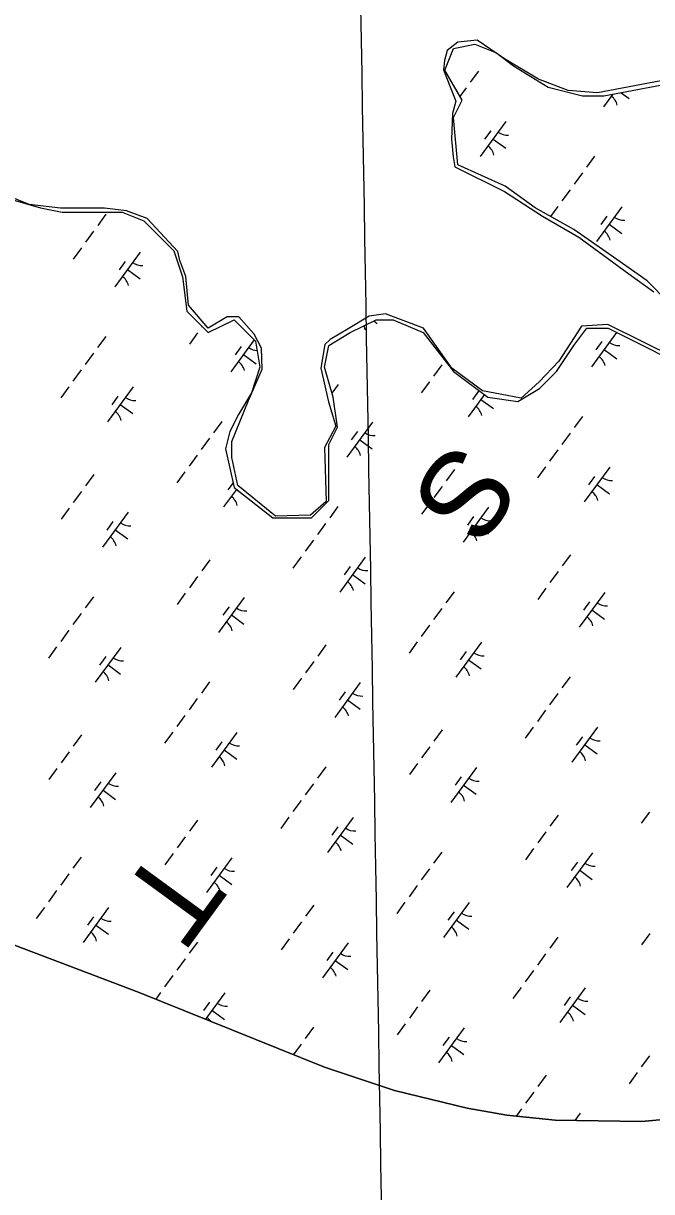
# Model space of a CAD drawing. Extents: x 3905714 to 3926767, y 183354 to 205755.
# Drawn here: x 3914338 to 3915064, y 194998 to 196348 of the extents above; entities that cross this region are included whole.
import ezdxf

# ---------------------------------------------------------------- set-up
doc = ezdxf.new("R2010")
doc.units = 0
for name, color, linetype in [('V-GRID-MAJR', 7, 'Continuous'), ('V-RIVR-IDEN', 7, 'Continuous'), ('V-TOPO-SHOR', 7, 'Continuous'), ('V-WETL-SWMP', 7, 'Continuous')]:
    doc.layers.add(name, color=color, linetype=linetype)

msp = doc.modelspace()

# ---------------------------------------------------------------- linework, layer by layer
at = {"layer": 'V-GRID-MAJR'}
msp.add_spline([(3914930.2, 184667.8), (3914884.1, 187327.4), (3914779.2, 193387.5), (3914694.6, 198275.9)], degree=3, dxfattribs=at)
at = {"layer": 'V-TOPO-SHOR'}
for points in [[(3915080.3, 196282.9), (3915001, 196267.7), (3914967.2, 196270.4), (3914932.7, 196283.7), (3914893.6, 196307.2), (3914861.8, 196328.8), (3914839.5, 196326.4), (3914827.3, 196316.6), (3914824.1, 196305.3), (3914822.9, 196294.3), (3914830.8, 196274.9), (3914837.3, 196258.2), (3914833.6, 196243.9), (3914832.3, 196214.2), (3914834.4, 196193.8), (3914836.2, 196182.3), (3914893.7, 196153.8), (3914937.5, 196125.2), (3914979.5, 196101.2), (3915037.2, 196058.9), (3915066, 196037.8)], [(3915091.6, 195961.1), (3915012.8, 196000.1), (3914982.6, 195998.4), (3914956.4, 195958), (3914933.6, 195933.8), (3914912.9, 195914.9), (3914896.6, 195918.3), (3914868.2, 195923.7), (3914832.8, 195949.7), (3914800.1, 195995.8), (3914756.2, 196012.6), (3914737, 196009.7), (3914712.7, 195995.1), (3914691.9, 195983), (3914685.9, 195977.2), (3914681.3, 195949.9), (3914690.2, 195911), (3914698.5, 195882.8), (3914685.6, 195858.2), (3914687.4, 195795.5), (3914669.2, 195779.9), (3914629, 195778.6), (3914585.2, 195814.2), (3914578.3, 195846.5), (3914578.3, 195865.2), (3914597.6, 195912.4), (3914613.7, 195948.4), (3914612.9, 195972.8), (3914604.4, 195989.2), (3914586.6, 196009.1), (3914572.9, 196008.9), (3914551.3, 195995.8), (3914528.4, 196022.7), (3914525.3, 196055.7), (3914518.5, 196074.3), (3914515.9, 196084.7), (3914480.6, 196122.5), (3914456.6, 196131.6), (3914431.5, 196134.6), (3914380.4, 196134.6), (3914344.3, 196138.9), (3914308.7, 196153)], [(3914307.8, 195290.6), (3914471.5, 195228.6), (3914685.7, 195142.2), (3914766.5, 195115.1), (3914850.5, 195094.7), (3914896.4, 195086.6), (3914952.2, 195081.1), (3915052, 195079.4), (3915135.6, 195087.3), (3915182.7, 195097.5), (3915234.5, 195117.5), (3915279.1, 195147.6), (3915332.6, 195191.7), (3915406.2, 195262.3), (3915585.5, 195470.7), (3915629.7, 195526.8), (3915716.6, 195642.8), (3915879.3, 195871.2)]]:
    msp.add_lwpolyline(points, dxfattribs=at)
at = {"layer": 'V-WETL-SWMP'}
for p, q in [((3914834.5, 196319), (3914859.4, 196323.9)), ((3914859.4, 196323.9), (3914884.2, 196314)), ((3914824.6, 196294.1), (3914834.5, 196319)), ((3914884.2, 196314), (3914904.1, 196299.1)), ((3914904.1, 196299.1), (3914943.9, 196274.2)), ((3914844.5, 196259.3), (3914824.6, 196294.1)), ((3914863.5, 196293), (3914854, 196280.1)), ((3914849.3, 196273.6), (3914842, 196263.6)), ((3914943.9, 196274.2), (3914983.6, 196264.3)), ((3915008.5, 196264.3), (3915088, 196279.2)), ((3914834.5, 196239.4), (3914844.5, 196259.3)), ((3914983.6, 196264.3), (3915008.5, 196264.3)), ((3915018.6, 196266.2), (3915008.1, 196251.8)), ((3915028.3, 196268), (3915037.4, 196261.4)), ((3914839.5, 196184.7), (3914834.5, 196239.4)), ((3914895.1, 196234.6), (3914865.6, 196194.2)), ((3914877.7, 196223.8), (3914870.6, 196214.1)), ((3914880.3, 196214.4), (3914894.9, 196203.8)), ((3914997.7, 196194.7), (3914988.2, 196181.8)), ((3914894.2, 196159.8), (3914839.5, 196184.7)), ((3914983.5, 196175.3), (3914974, 196162.4)), ((3914929, 196135), (3914894.2, 196159.8)), ((3914969.3, 196155.9), (3914959.8, 196143)), ((3914322.7, 196144.9), (3914357.4, 196135)), ((3914357.4, 196135), (3914382.3, 196130)), ((3914973.7, 196110.1), (3914929, 196135)), ((3914955.1, 196136.6), (3914946.7, 196125.1)), ((3915029.3, 196136.3), (3914999.7, 196095.9)), ((3914382.3, 196130), (3914451.9, 196130)), ((3914433, 196127.5), (3914423.6, 196114.6)), ((3914451.9, 196130), (3914476.7, 196120.1)), ((3915011.8, 196125.5), (3915004.7, 196115.8)), ((3914418.8, 196108.1), (3914409.4, 196095.2)), ((3914476.7, 196120.1), (3914511.5, 196085.3)), ((3915023.4, 196075.3), (3914973.7, 196110.1)), ((3915014.5, 196116.1), (3915029, 196105.4)), ((3914404.7, 196088.7), (3914395.2, 196075.8)), ((3914472.7, 196083.9), (3914443.1, 196043.6)), ((3914511.5, 196085.3), (3914521.4, 196055.4)), ((3914455.2, 196073.1), (3914448.1, 196063.5)), ((3915058.2, 196050.5), (3915023.4, 196075.3)), ((3914457.9, 196063.7), (3914472.4, 196053.1)), ((3914521.4, 196055.4), (3914526.4, 196015.7)), ((3915083, 196025.6), (3915058.2, 196050.5)), ((3914526.4, 196015.7), (3914551.3, 195990.8)), ((3914551.3, 195990.8), (3914581.1, 196005.7)), ((3914581.1, 196005.7), (3914605.9, 195980.8)), ((3914715.3, 195990.8), (3914745.1, 196005.7)), ((3914742.4, 196004.4), (3914746.5, 196001.3)), ((3914745.1, 196005.7), (3914765, 196005.7)), ((3914765, 196005.7), (3914799.7, 195990.8)), ((3914432.7, 195986.4), (3914423.2, 195973.5)), ((3914538.8, 195990.4), (3914529.4, 195977.5)), ((3914544.2, 195997.8), (3914543.6, 195996.9)), ((3914690.4, 195975.9), (3914715.3, 195990.8)), ((3914799.7, 195990.8), (3914834.5, 195946)), ((3914973.7, 195975.9), (3914988.6, 195995.8)), ((3914988.6, 195995.8), (3915013.4, 195995.8)), ((3915023.1, 195990.9), (3914994, 195951.1)), ((3915013.4, 195995.8), (3915043.3, 195980.8)), ((3914604.4, 195982.3), (3914577.3, 195945.3)), ((3914589.4, 195974.8), (3914582.3, 195965.2)), ((3914605.9, 195980.8), (3914610.9, 195951)), ((3914685.4, 195951), (3914690.4, 195975.9)), ((3914953.8, 195946), (3914973.7, 195975.9)), ((3915006.1, 195980.7), (3914999, 195971)), ((3915043.3, 195980.8), (3915093, 195956)), ((3914418.5, 195967), (3914409, 195954.1)), ((3914592.1, 195965.4), (3914606.6, 195954.8)), ((3915008.7, 195971.3), (3915023.3, 195960.6)), ((3914404.3, 195947.7), (3914394.8, 195934.8)), ((3914610.9, 195951), (3914601, 195921.2)), ((3914695.4, 195916.2), (3914685.4, 195951)), ((3914821, 195953.5), (3914811.5, 195940.6)), ((3914834.5, 195946), (3914874.3, 195916.2)), ((3914933.9, 195926.1), (3914953.8, 195946)), ((3914806.8, 195934.1), (3914797.3, 195921.2)), ((3914390.1, 195928.3), (3914380.7, 195915.4)), ((3914464.3, 195928), (3914434.8, 195887.7)), ((3914601, 195921.2), (3914586, 195896.3)), ((3914701.4, 195930.9), (3914694.1, 195920.8)), ((3914870.3, 195919.2), (3914851.4, 195893.5)), ((3914863.5, 195923), (3914856.4, 195913.4)), ((3914909.1, 195911.2), (3914933.9, 195926.1)), ((3914446.9, 195917.2), (3914439.8, 195907.5)), ((3914449.5, 195907.8), (3914464, 195897.2)), ((3914700.4, 195881.4), (3914695.4, 195916.2)), ((3914866.2, 195913.6), (3914880.7, 195903)), ((3914874.3, 195916.2), (3914909.1, 195911.2)), ((3914586, 195896.3), (3914576.1, 195876.4)), ((3914983.5, 195893.9), (3914974.1, 195881)), ((3914566.9, 195888.1), (3914557.4, 195875.2)), ((3914690.4, 195861.5), (3914700.4, 195881.4)), ((3914741, 195887.3), (3914711.5, 195847)), ((3914552.7, 195868.7), (3914543.2, 195855.8)), ((3914576.1, 195876.4), (3914571.1, 195856.5)), ((3914723.6, 195876.5), (3914716.5, 195866.9)), ((3914726.2, 195867.1), (3914740.8, 195856.5)), ((3914969.3, 195874.6), (3914959.9, 195861.7)), ((3914571.1, 195856.5), (3914581.1, 195811.8)), ((3914690.4, 195831.7), (3914690.4, 195861.5)), ((3914955.2, 195855.2), (3914945.7, 195842.3)), ((3914538.5, 195849.4), (3914529, 195836.5)), ((3914418.9, 195826.7), (3914409.4, 195813.8)), ((3914524.3, 195830), (3914514.8, 195817.1)), ((3914690.4, 195796.9), (3914690.4, 195831.7)), ((3914835.6, 195832.5), (3914826.1, 195819.6)), ((3914941, 195835.8), (3914931.5, 195822.9)), ((3915015.2, 195835.5), (3914985.6, 195795.2)), ((3914997.7, 195824.7), (3914990.6, 195815.1)), ((3914579.9, 195817.3), (3914573.9, 195809.2)), ((3914581.1, 195811.8), (3914625.8, 195777)), ((3914821.4, 195813.2), (3914811.9, 195800.3)), ((3915000.4, 195815.3), (3915014.9, 195804.7)), ((3914404.7, 195807.4), (3914395.2, 195794.5)), ((3914583.8, 195809.7), (3914568.9, 195789.4)), ((3914583.7, 195809.5), (3914588.6, 195805.9)), ((3914390.5, 195788), (3914381.1, 195775.1)), ((3914670.5, 195777), (3914690.4, 195796.9)), ((3914701, 195789.8), (3914691.6, 195776.9)), ((3914807.2, 195793.8), (3914797.7, 195780.9)), ((3914875.2, 195789), (3914845.7, 195748.7)), ((3914458.5, 195783.2), (3914429, 195742.8)), ((3914441.1, 195772.4), (3914434, 195762.7)), ((3914625.8, 195777), (3914670.5, 195777)), ((3914686.8, 195770.4), (3914677.4, 195757.5)), ((3914857.7, 195778.2), (3914850.7, 195768.5)), ((3914443.8, 195763), (3914458.3, 195752.4)), ((3914860.4, 195768.8), (3914874.9, 195758.2)), ((3914672.7, 195751.1), (3914663.2, 195738.2)), ((3914658.5, 195731.7), (3914649, 195718.8)), ((3914732.7, 195731.4), (3914703.1, 195691)), ((3914969.7, 195734.2), (3914960.3, 195721.3)), ((3914553.1, 195728.4), (3914543.6, 195715.5)), ((3914715.2, 195720.6), (3914708.1, 195710.9)), ((3914538.9, 195709.1), (3914529.4, 195696.1)), ((3914717.9, 195711.2), (3914732.4, 195700.6)), ((3914955.6, 195714.9), (3914946.1, 195702)), ((3914524.7, 195689.7), (3914515.2, 195676.8)), ((3914835.2, 195691.5), (3914825.8, 195678.6)), ((3914941.4, 195695.5), (3914931.9, 195682.6)), ((3915009.4, 195690.7), (3914979.8, 195650.4)), ((3914418.5, 195685.7), (3914409.1, 195672.7)), ((3914592.7, 195684.9), (3914563.2, 195644.5)), ((3914991.9, 195679.9), (3914984.8, 195670.2)), ((3914404.4, 195666.3), (3914394.9, 195653.4)), ((3914575.3, 195674.1), (3914568.2, 195664.4)), ((3914577.9, 195664.7), (3914592.5, 195654.1)), ((3914821, 195672.1), (3914811.6, 195659.2)), ((3914994.6, 195670.5), (3915009.1, 195659.9)), ((3914806.8, 195652.8), (3914797.4, 195639.9)), ((3914390.2, 195646.9), (3914380.7, 195634)), ((3914376, 195627.6), (3914366.5, 195614.7)), ((3914450.2, 195627.2), (3914420.6, 195586.9)), ((3914687.2, 195630.1), (3914677.8, 195617.2)), ((3914792.7, 195633.4), (3914783.2, 195620.5)), ((3914866.8, 195633.1), (3914837.3, 195592.7)), ((3914849.4, 195622.3), (3914842.3, 195612.6)), ((3914432.7, 195616.5), (3914425.6, 195606.8)), ((3914673.1, 195610.7), (3914663.6, 195597.8)), ((3914852.1, 195612.9), (3914866.6, 195602.3)), ((3914435.4, 195607.1), (3914449.9, 195596.4)), ((3914552.7, 195587.3), (3914543.3, 195574.4)), ((3914658.9, 195591.4), (3914649.4, 195578.5)), ((3914726.9, 195586.6), (3914697.3, 195546.2)), ((3914969.4, 195593.2), (3914959.9, 195580.3)), ((3914538.5, 195568), (3914529.1, 195555.1)), ((3914709.4, 195575.8), (3914702.3, 195566.1)), ((3914955.2, 195573.8), (3914945.7, 195560.9)), ((3914712.1, 195566.4), (3914726.6, 195555.8)), ((3914941, 195554.5), (3914931.6, 195541.5)), ((3914524.3, 195548.6), (3914514.9, 195535.7)), ((3914510.2, 195529.3), (3914500.7, 195516.4)), ((3914584.3, 195528.9), (3914554.8, 195488.6)), ((3914821.4, 195531.8), (3914812, 195518.9)), ((3914926.8, 195535.1), (3914917.4, 195522.2)), ((3915001, 195534.8), (3914971.5, 195494.4)), ((3914404.8, 195526), (3914395.3, 195513.1)), ((3914566.9, 195518.2), (3914559.8, 195508.5)), ((3914983.6, 195524), (3914976.5, 195514.3)), ((3914986.2, 195514.6), (3915000.8, 195504)), ((3914390.6, 195506.6), (3914381.1, 195493.7)), ((3914569.6, 195508.8), (3914584.1, 195498.1)), ((3914807.2, 195512.4), (3914797.8, 195499.5)), ((3914376.4, 195487.3), (3914366.9, 195474.4)), ((3914686.9, 195489), (3914677.4, 195476.1)), ((3914793.1, 195493.1), (3914783.6, 195480.2)), ((3914861.1, 195488.3), (3914831.5, 195447.9)), ((3914444.4, 195482.4), (3914414.8, 195442.1)), ((3914843.6, 195477.5), (3914836.5, 195467.8)), ((3914426.9, 195471.7), (3914419.8, 195462)), ((3914429.6, 195462.3), (3914444.1, 195451.6)), ((3914672.7, 195469.7), (3914663.3, 195456.8)), ((3914846.3, 195468.1), (3914860.8, 195457.4)), ((3914658.5, 195450.3), (3914649.1, 195437.4)), ((3914955.6, 195433.5), (3914946.1, 195420.6)), ((3915061, 195436.8), (3915051.6, 195423.9)), ((3914538.9, 195427.7), (3914529.5, 195414.8)), ((3914644.3, 195431), (3914634.9, 195418.1)), ((3914718.5, 195430.6), (3914689, 195390.3)), ((3914701.1, 195419.9), (3914694, 195410.2)), ((3914524.7, 195408.3), (3914515.3, 195395.4)), ((3914703.8, 195410.5), (3914718.3, 195399.8)), ((3914941.4, 195414.1), (3914932, 195401.2)), ((3914927.2, 195394.8), (3914917.8, 195381.9)), ((3914404.4, 195384.9), (3914394.9, 195372)), ((3914510.6, 195389), (3914501.1, 195376)), ((3914578.6, 195384.1), (3914549, 195343.8)), ((3914821.1, 195390.7), (3914811.6, 195377.8)), ((3914995.2, 195389.9), (3914965.7, 195349.6)), ((3914977.8, 195379.2), (3914970.7, 195369.5)), ((3914390.2, 195365.6), (3914380.8, 195352.6)), ((3914561.1, 195373.4), (3914554, 195363.7)), ((3914806.9, 195371.4), (3914797.4, 195358.5)), ((3914980.5, 195369.8), (3914995, 195359.1)), ((3914563.8, 195364), (3914578.3, 195353.3)), ((3914792.7, 195352), (3914783.3, 195339.1)), ((3914376, 195346.2), (3914366.6, 195333.3)), ((3914361.8, 195326.8), (3914352.4, 195313.9)), ((3914436, 195326.5), (3914406.5, 195286.2)), ((3914673.1, 195329.4), (3914663.7, 195316.5)), ((3914778.5, 195332.7), (3914769.1, 195319.8)), ((3914852.7, 195332.3), (3914823.2, 195292)), ((3914418.6, 195315.7), (3914411.5, 195306.1)), ((3914835.3, 195321.6), (3914828.2, 195311.9)), ((3914837.9, 195312.2), (3914852.5, 195301.5)), ((3914421.3, 195306.3), (3914435.8, 195295.7)), ((3914658.9, 195310), (3914649.5, 195297.1)), ((3914471.5, 195228.6), (3914307.8, 195290.6)), ((3914538.6, 195286.6), (3914529.1, 195273.7)), ((3914644.7, 195290.6), (3914635.3, 195277.7)), ((3914712.8, 195285.8), (3914683.2, 195245.5)), ((3914955.3, 195292.4), (3914945.8, 195279.5)), ((3915061.4, 195296.5), (3915052, 195283.6)), ((3914695.3, 195275), (3914688.2, 195265.4)), ((3914941.1, 195273.1), (3914931.6, 195260.2)), ((3914524.4, 195267.2), (3914514.9, 195254.3)), ((3914698, 195265.6), (3914712.5, 195255)), ((3914510.2, 195247.9), (3914500.8, 195235)), ((3914926.9, 195253.7), (3914917.4, 195240.8)), ((3914807.3, 195231.1), (3914797.8, 195218.2)), ((3914912.7, 195234.4), (3914903.2, 195221.4)), ((3914986.9, 195234), (3914957.3, 195193.7)), ((3914685.7, 195142.2), (3914471.5, 195228.6)), ((3914496, 195228.5), (3914490.5, 195220.9)), ((3914552.8, 195217.4), (3914545.7, 195207.8)), ((3914570.2, 195228.2), (3914547.9, 195197.7)), ((3914969.4, 195223.3), (3914962.3, 195213.6)), ((3914555.4, 195208), (3914570, 195197.4)), ((3914793.1, 195211.7), (3914783.7, 195198.8)), ((3914972.1, 195213.9), (3914986.6, 195203.2)), ((3914778.9, 195192.3), (3914769.5, 195179.4)), ((3914672.8, 195188.3), (3914663.3, 195175.4)), ((3914846.9, 195187.5), (3914817.4, 195147.2)), ((3914829.5, 195176.7), (3914822.4, 195167.1)), ((3914658.6, 195168.9), (3914649.6, 195156.7)), ((3914832.2, 195167.3), (3914846.7, 195156.7)), ((3915061.1, 195155.4), (3915051.6, 195142.5)), ((3914766.5, 195115.1), (3914685.7, 195142.2)), ((3915046.9, 195136), (3915037.4, 195123.1)), ((3914941.5, 195132.8), (3914932, 195119.8)), ((3914850.5, 195094.7), (3914766.5, 195115.1)), ((3914927.3, 195113.4), (3914917.8, 195100.5)), ((3914896.4, 195086.6), (3914850.5, 195094.7)), ((3914952.2, 195081.1), (3914896.4, 195086.6)), ((3914913.1, 195094), (3914906.9, 195085.6)), ((3914981.1, 195089.2), (3914974.9, 195080.7)), ((3915135.6, 195087.3), (3915052, 195079.4)), ((3915052, 195079.4), (3914952.2, 195081.1))]:
    msp.add_line(p, q, dxfattribs=at)
for centre, start, end in [((3915006.7, 196249.6), 13, 54.5436), ((3914896.9, 196236.5), 233, 274.5436), ((3914864.2, 196192), 13, 54.5436), ((3915031, 196138.2), 233, 274.5436), ((3914998.4, 196093.7), 13, 54.5436), ((3914474.4, 196085.9), 233, 274.5436), ((3914441.8, 196041.3), 13, 54.5436), ((3914715.9, 195989.5), 13, 31.1544), ((3914608.6, 195987.6), 233, 267.2471), ((3915025.3, 195993.4), 233, 274.5436), ((3914992.6, 195948.8), 13, 54.5436), ((3914575.9, 195943), 13, 54.5436), ((3914466, 195930), 233, 274.5436), ((3914850.1, 195891.2), 13, 54.5436), ((3914433.4, 195885.4), 13, 54.5436), ((3914742.8, 195889.3), 233, 274.5436), ((3914710.1, 195844.7), 13, 54.5436), ((3915016.9, 195837.5), 233, 274.5436), ((3914567.6, 195787.1), 13, 54.5436), ((3914984.2, 195792.9), 13, 54.5436), ((3914460.3, 195785.1), 233, 274.5436), ((3914876.9, 195791), 233, 274.5436), ((3914844.3, 195746.4), 13, 54.5436), ((3914427.6, 195740.6), 13, 54.5436), ((3914734.4, 195733.4), 233, 274.5436), ((3914701.8, 195688.8), 13, 54.5436), ((3915011.1, 195692.7), 233, 274.5436), ((3914594.4, 195686.8), 233, 274.5436), ((3914978.5, 195648.1), 13, 54.5436), ((3914561.8, 195642.3), 13, 54.5436), ((3914451.9, 195629.2), 233, 274.5436), ((3914868.6, 195635), 233, 274.5436), ((3914419.3, 195584.7), 13, 54.5436), ((3914835.9, 195590.5), 13, 54.5436), ((3914728.6, 195588.5), 233, 274.5436), ((3914696, 195544), 13, 54.5436), ((3914586.1, 195530.9), 233, 274.5436), ((3915002.8, 195536.7), 233, 274.5436), ((3914553.4, 195486.4), 13, 54.5436), ((3914970.1, 195492.2), 13, 54.5436), ((3914862.8, 195490.2), 233, 274.5436), ((3914446.1, 195484.4), 233, 274.5436), ((3914830.2, 195445.7), 13, 54.5436), ((3914413.5, 195439.8), 13, 54.5436), ((3914720.3, 195432.6), 233, 274.5436), ((3914687.6, 195388), 13, 54.5436), ((3914580.3, 195386.1), 233, 274.5436), ((3914997, 195391.9), 233, 274.5436), ((3914547.7, 195341.5), 13, 54.5436), ((3914964.3, 195347.4), 13, 54.5436), ((3914437.8, 195328.5), 233, 274.5436), ((3914854.4, 195334.3), 233, 274.5436), ((3914405.1, 195283.9), 13, 54.5436), ((3914821.8, 195289.7), 13, 54.5436), ((3914714.5, 195287.8), 233, 274.5436), ((3914681.8, 195243.2), 13, 54.5436), ((3914988.6, 195236), 233, 274.5436), ((3914572, 195230.2), 233, 274.5436), ((3914956, 195191.4), 13, 54.5436), ((3914539.3, 195185.6), 33.2414, 54.5436), ((3914848.7, 195189.5), 233, 274.5436), ((3914816, 195144.9), 13, 54.5436)]:
    msp.add_arc(centre, 17.6, start, end, dxfattribs=at)

# ---------------------------------------------------------------- texts
at = {"layer": 'V-RIVR-IDEN'}
for s, p in [('S', (3914834.5, 195869.6)), ('T', (3914493.8, 195402.8))]:
    msp.add_text(s, height=100, rotation=233.8714, dxfattribs=at).set_placement(p)

doc.saveas('drawing.dxf')
